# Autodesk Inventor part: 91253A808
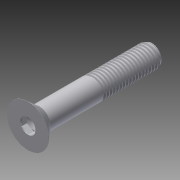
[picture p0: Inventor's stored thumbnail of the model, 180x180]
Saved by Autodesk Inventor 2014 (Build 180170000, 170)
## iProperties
Company: NHTSA/VRTC
Created: 2012-08
Material: Steel, Mild
Document SubType Name: Modeling
Designer: Mike Vanvoorhis
Density: 7.86 g/cm^3
Mass: 141.687 g
Surface Area: 66.4947 cm^2
Volume: 18.0264 cm^3
Description: SCREW, FHCS 5/8-11 x 3 1/2"
Project: CHILD sIDE iMPACT sLED
Stock Number: 91253A808
Appearance: Steel
Translation Standard: IGES 5.3
FileName: C:\SW Working Folder\Fixes\91253A808.igs
PreProcessor: SolidWorks 2003 by SolidWorks Corporation
PostProcessor: Build: 160, Release: 2012 RTM - Date: Tue 03/01/2011
Sent Units: inch
Uncertainty: 1e-08
Author: Dave Walker
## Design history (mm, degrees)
node "91253A808.IGS1"
node "91253A808"
node "Base1"
